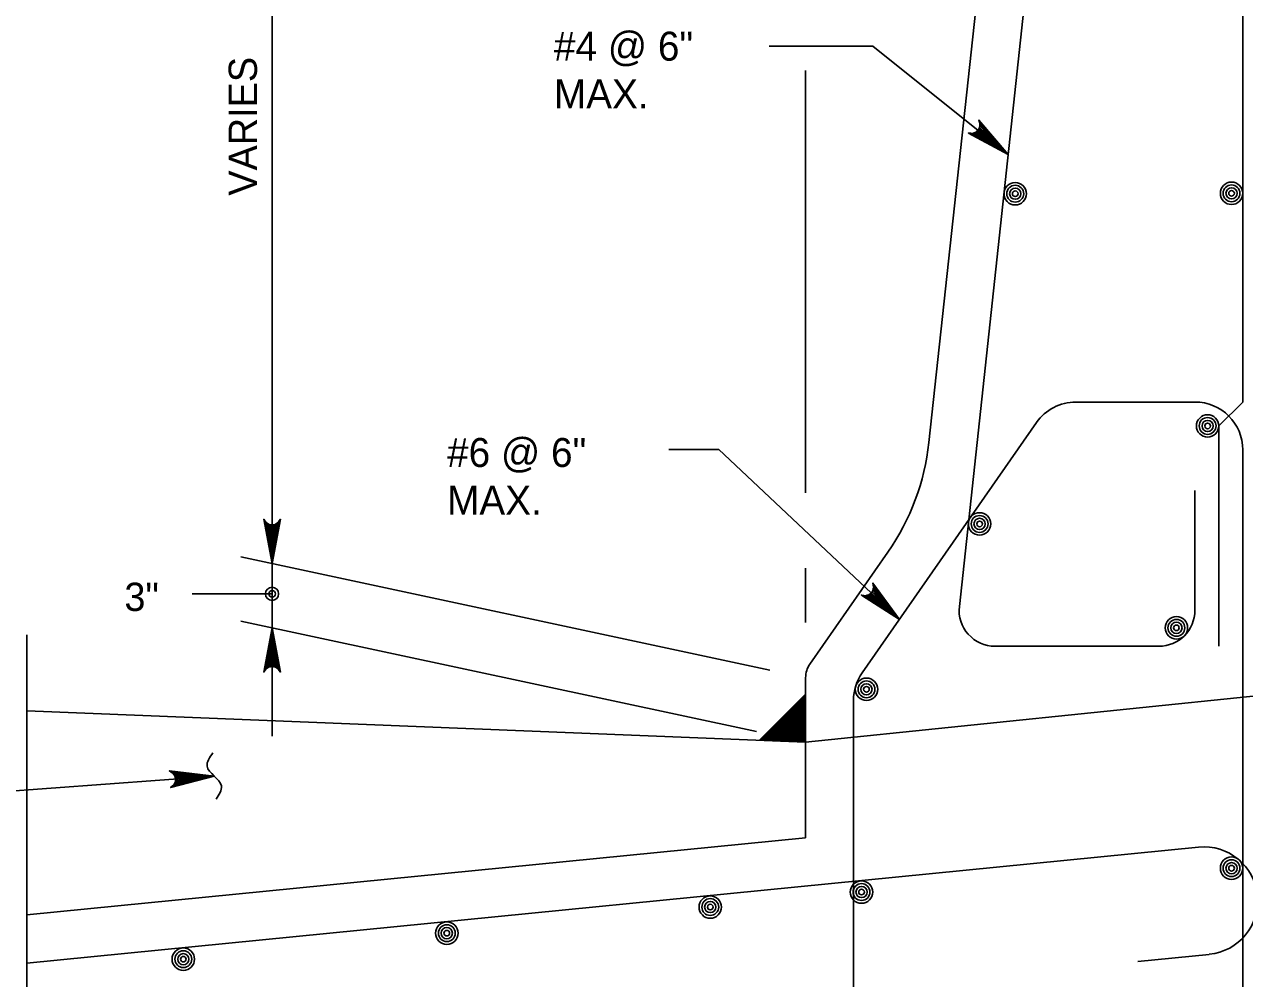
# Model space of a CAD drawing. Extents: x 638167 to 640248, y 296544 to 298920.
# Drawn here: x 639614.9 to 639744.3, y 297561.4 to 297662.6 of the extents above; entities that cross this region are included whole.
import ezdxf

# ---------------------------------------------------------------- set-up
doc = ezdxf.new("R2010")
doc.units = 0
for name, color, linetype in [('1', 7, 'Continuous'), ('50', 7, 'Continuous'), ('57', 7, 'Continuous')]:
    doc.layers.add(name, color=color, linetype=linetype)

# ---------------------------------------------------------------- blocks, each defined once
blk = doc.blocks.new('DIMDOT')
at = {"layer": '57'}
for radius in [2, 1]:
    blk.add_circle((0, 0), radius, dxfattribs=at)
blk = doc.blocks.new('BAR')
at = {"layer": '50'}
for radius in [2, 1.5, 1, 0.5]:
    blk.add_circle((0, 0), radius, dxfattribs=at)

msp = doc.modelspace()

# ---------------------------------------------------------------- linework, layer by layer
at = {"layer": '1'}
for p, q in [((639641.2, 297587.07), (639641.2, 297705.25)), ((639718.74, 297691.24), (639710.86, 297618.23)), ((639723.14, 297684.65), (639714.09, 297600.83)), ((639744.14, 297622.52), (639744.14, 297684.25)), ((639704.92, 297660.27), (639693.92, 297660.27)), ((639704.92, 297660.27), (639719.26, 297648.78)), ((639697.78, 297612.87), (639697.78, 297657.69)), ((639739.06, 297622.52), (639726.44, 297622.52)), ((639744.14, 297622.52), (639741.6, 297619.98)), ((639722.27, 297620.34), (639703.78, 297593.79)), ((639741.6, 297596.62), (639741.6, 297619.98)), ((639688.56, 297617.47), (639683.26, 297617.47)), ((639688.56, 297617.47), (639707.73, 297599.46)), ((639744.14, 297527.71), (639744.14, 297617.44)), ((639739.06, 297613.13), (639739.06, 297600.43)), ((639706.5, 297606.59), (639698.24, 297594.73)), ((639693.97, 297594.09), (639637.88, 297606.1)), ((639697.78, 297599.15), (639697.78, 297604.91)), ((639641.2, 297602.17), (639632.73, 297602.17)), ((639692.57, 297587.57), (639637.88, 297599.28)), ((639615.18, 297552.37), (639615.18, 297597.82)), ((639717.87, 297596.62), (639735.25, 297596.62)), ((639697.78, 297593.28), (639697.78, 297576.3)), ((639692.9, 297586.65), (639697.78, 297591.54)), ((639697.49, 297591.09), (639696.65, 297590.24)), ((639697.35, 297591.09), (639696.65, 297590.38)), ((639697.64, 297591.09), (639696.65, 297590.1)), ((639697.78, 297591.09), (639696.79, 297590.1)), ((639697.35, 297590.1), (639696.85, 297590.6)), ((639697.49, 297590.1), (639696.92, 297590.67)), ((639697.78, 297590.95), (639696.93, 297590.1)), ((639697.64, 297590.1), (639696.99, 297590.74)), ((639697.78, 297590.1), (639697.06, 297590.81)), ((639697.78, 297590.81), (639697.07, 297590.1)), ((639697.78, 297590.23), (639697.13, 297590.88)), ((639697.78, 297590.37), (639697.2, 297590.95)), ((639697.78, 297590.67), (639697.21, 297590.1)), ((639697.78, 297590.51), (639697.27, 297591.02)), ((639697.35, 297591.09), (639697.34, 297591.09)), ((639697.78, 297591.52), (639697.35, 297591.09)), ((639697.78, 297590.65), (639697.35, 297591.09)), ((639697.49, 297591.09), (639697.41, 297591.17)), ((639697.78, 297591.38), (639697.49, 297591.09)), ((639697.64, 297591.09), (639697.49, 297591.24)), ((639697.78, 297590.8), (639697.49, 297591.09)), ((639697.78, 297591.09), (639697.56, 297591.31)), ((639697.78, 297591.22), (639697.63, 297591.38)), ((639697.78, 297591.24), (639697.64, 297591.09)), ((639697.78, 297590.94), (639697.64, 297591.09)), ((639697.78, 297591.36), (639697.7, 297591.45)), ((639697.78, 297591.5), (639697.77, 297591.52)), ((639697.78, 297586.46), (639747.31, 297591.54)), ((639697.78, 297591.08), (639697.78, 297591.09)), ((639697.78, 297591.09), (639697.78, 297591.09)), ((639702.86, 297590.89), (639702.86, 297543.27)), ((639615.18, 297589.76), (639697.78, 297586.46)), ((639696.36, 297590.1), (639695.37, 297589.11)), ((639696.5, 297590.1), (639695.51, 297589.11)), ((639695.8, 297589.11), (639695.58, 297589.33)), ((639695.94, 297589.11), (639695.65, 297589.4)), ((639696.65, 297590.1), (639695.66, 297589.11)), ((639696.08, 297589.11), (639695.72, 297589.47)), ((639696.22, 297589.11), (639695.79, 297589.54)), ((639696.65, 297589.95), (639695.8, 297589.11)), ((639696.36, 297589.11), (639695.86, 297589.61)), ((639696.5, 297589.11), (639695.93, 297589.68)), ((639696.65, 297589.81), (639695.94, 297589.11)), ((639696.65, 297589.11), (639696, 297589.75)), ((639696.65, 297589.25), (639696.07, 297589.82)), ((639696.65, 297589.67), (639696.08, 297589.11)), ((639696.65, 297589.39), (639696.14, 297589.89)), ((639696.65, 297589.53), (639696.21, 297589.96)), ((639696.65, 297589.53), (639696.22, 297589.11)), ((639696.65, 297589.67), (639696.28, 297590.03)), ((639696.36, 297590.1), (639696.35, 297590.1)), ((639696.65, 297590.38), (639696.36, 297590.1)), ((639696.65, 297589.81), (639696.36, 297590.1)), ((639696.65, 297589.39), (639696.36, 297589.11)), ((639696.5, 297590.1), (639696.42, 297590.18)), ((639696.65, 297590.1), (639696.5, 297590.25)), ((639696.65, 297590.24), (639696.5, 297590.1)), ((639696.65, 297589.95), (639696.5, 297590.1)), ((639696.65, 297590.24), (639696.57, 297590.32)), ((639696.65, 297590.38), (639696.64, 297590.39)), ((639696.93, 297590.1), (639696.65, 297590.38)), ((639696.79, 297590.1), (639696.65, 297590.24)), ((639697.49, 297590.1), (639696.65, 297589.25)), ((639697.35, 297590.1), (639696.65, 297589.39)), ((639697.21, 297590.1), (639696.65, 297589.53)), ((639697.07, 297590.1), (639696.65, 297589.67)), ((639696.93, 297590.1), (639696.65, 297589.81)), ((639696.79, 297590.1), (639696.65, 297589.95)), ((639697.64, 297590.1), (639696.65, 297589.11)), ((639697.64, 297589.11), (639696.65, 297590.1)), ((639697.49, 297589.11), (639696.65, 297589.95)), ((639697.35, 297589.11), (639696.65, 297589.81)), ((639697.21, 297589.11), (639696.65, 297589.67)), ((639697.07, 297589.11), (639696.65, 297589.53)), ((639696.93, 297589.11), (639696.65, 297589.39)), ((639697.07, 297590.1), (639696.71, 297590.46)), ((639697.21, 297590.1), (639696.78, 297590.53)), ((639697.78, 297590.1), (639696.79, 297589.11)), ((639697.78, 297589.11), (639696.79, 297590.1)), ((639697.78, 297589.24), (639696.93, 297590.1)), ((639697.78, 297589.96), (639696.93, 297589.11)), ((639697.78, 297589.38), (639697.07, 297590.1)), ((639697.78, 297589.82), (639697.07, 297589.11)), ((639697.78, 297589.52), (639697.21, 297590.1)), ((639697.78, 297589.68), (639697.21, 297589.11)), ((639697.78, 297590.53), (639697.35, 297590.1)), ((639697.78, 297589.66), (639697.35, 297590.1)), ((639697.78, 297589.54), (639697.35, 297589.11)), ((639697.78, 297590.39), (639697.49, 297590.1)), ((639697.78, 297589.81), (639697.49, 297590.1)), ((639697.78, 297589.4), (639697.49, 297589.11)), ((639697.78, 297590.25), (639697.64, 297590.1)), ((639697.78, 297589.95), (639697.64, 297590.1)), ((639697.78, 297590.09), (639697.78, 297590.1)), ((639697.78, 297590.1), (639697.78, 297590.1)), ((639694.38, 297588.12), (639693.39, 297587.13)), ((639694.52, 297588.12), (639693.53, 297587.13)), ((639694.67, 297588.12), (639693.68, 297587.13)), ((639694.67, 297587.69), (639694.3, 297588.05)), ((639694.38, 297588.12), (639694.37, 297588.12)), ((639694.67, 297588.4), (639694.38, 297588.12)), ((639694.67, 297587.83), (639694.38, 297588.12)), ((639694.52, 297588.12), (639694.44, 297588.2)), ((639694.67, 297588.12), (639694.52, 297588.27)), ((639694.67, 297588.26), (639694.52, 297588.12)), ((639694.67, 297587.97), (639694.52, 297588.12)), ((639694.67, 297588.26), (639694.59, 297588.34)), ((639694.67, 297588.4), (639694.66, 297588.41)), ((639695.51, 297589.11), (639694.67, 297588.26)), ((639695.37, 297589.11), (639694.67, 297588.4)), ((639695.66, 297589.11), (639694.67, 297588.12)), ((639694.95, 297588.12), (639694.67, 297588.4)), ((639694.81, 297588.12), (639694.67, 297588.26)), ((639695.51, 297588.12), (639694.67, 297587.27)), ((639695.37, 297588.12), (639694.67, 297587.41)), ((639695.23, 297588.12), (639694.67, 297587.55)), ((639695.09, 297588.12), (639694.67, 297587.69)), ((639694.95, 297588.12), (639694.67, 297587.83)), ((639694.81, 297588.12), (639694.67, 297587.97)), ((639695.66, 297588.12), (639694.67, 297587.13)), ((639695.66, 297587.13), (639694.67, 297588.12)), ((639695.09, 297588.12), (639694.73, 297588.48)), ((639695.23, 297588.12), (639694.8, 297588.55)), ((639695.8, 297589.11), (639694.81, 297588.12)), ((639695.8, 297588.12), (639694.81, 297587.13)), ((639695.8, 297587.13), (639694.81, 297588.12)), ((639695.37, 297588.12), (639694.87, 297588.62)), ((639695.51, 297588.12), (639694.94, 297588.69)), ((639695.94, 297589.11), (639694.95, 297588.12)), ((639695.94, 297588.12), (639694.95, 297587.13)), ((639695.94, 297587.13), (639694.95, 297588.12)), ((639695.66, 297588.12), (639695.01, 297588.76)), ((639695.8, 297588.12), (639695.08, 297588.83)), ((639696.08, 297589.11), (639695.09, 297588.12)), ((639696.08, 297588.12), (639695.09, 297587.13)), ((639696.08, 297587.13), (639695.09, 297588.12)), ((639695.94, 297588.12), (639695.15, 297588.9)), ((639696.08, 297588.12), (639695.22, 297588.97)), ((639696.22, 297589.11), (639695.23, 297588.12)), ((639696.22, 297588.12), (639695.23, 297587.13)), ((639696.22, 297587.13), (639695.23, 297588.12)), ((639696.22, 297588.12), (639695.29, 297589.04)), ((639695.37, 297589.11), (639695.36, 297589.11)), ((639696.36, 297589.11), (639695.37, 297588.12)), ((639696.36, 297588.12), (639695.37, 297589.11)), ((639696.36, 297588.12), (639695.37, 297587.13)), ((639696.36, 297587.13), (639695.37, 297588.12)), ((639695.51, 297589.11), (639695.43, 297589.19)), ((639695.66, 297589.11), (639695.51, 297589.26)), ((639696.5, 297589.11), (639695.51, 297588.12)), ((639696.5, 297588.12), (639695.51, 297589.11)), ((639696.5, 297588.12), (639695.51, 297587.13)), ((639696.5, 297587.13), (639695.51, 297588.12)), ((639696.65, 297588.12), (639695.66, 297589.11)), ((639696.65, 297589.11), (639695.66, 297588.12)), ((639696.65, 297587.13), (639695.66, 297588.12)), ((639696.65, 297588.12), (639695.66, 297587.13)), ((639696.65, 297588.26), (639695.8, 297589.11)), ((639696.65, 297588.96), (639695.8, 297588.12)), ((639696.65, 297587.27), (639695.8, 297588.12)), ((639696.65, 297588.4), (639695.94, 297589.11)), ((639696.65, 297588.82), (639695.94, 297588.12)), ((639696.65, 297587.41), (639695.94, 297588.12)), ((639696.65, 297588.54), (639696.08, 297589.11)), ((639696.65, 297588.68), (639696.08, 297588.12)), ((639696.65, 297587.55), (639696.08, 297588.12)), ((639696.65, 297588.68), (639696.22, 297589.11)), ((639696.65, 297588.54), (639696.22, 297588.12)), ((639696.65, 297587.69), (639696.22, 297588.12)), ((639696.65, 297588.82), (639696.36, 297589.11)), ((639696.65, 297588.4), (639696.36, 297588.12)), ((639696.65, 297587.83), (639696.36, 297588.12)), ((639696.65, 297589.25), (639696.5, 297589.11)), ((639696.65, 297588.96), (639696.5, 297589.11)), ((639696.65, 297588.26), (639696.5, 297588.12)), ((639696.65, 297587.97), (639696.5, 297588.12)), ((639696.79, 297589.11), (639696.65, 297589.25)), ((639697.49, 297589.11), (639696.65, 297588.26)), ((639697.35, 297589.11), (639696.65, 297588.4)), ((639697.21, 297589.11), (639696.65, 297588.54)), ((639697.07, 297589.11), (639696.65, 297588.68)), ((639696.93, 297589.11), (639696.65, 297588.82)), ((639696.79, 297589.11), (639696.65, 297588.96)), ((639697.64, 297589.11), (639696.65, 297588.12)), ((639697.64, 297588.12), (639696.65, 297589.11)), ((639697.49, 297588.12), (639696.65, 297588.96)), ((639697.35, 297588.12), (639696.65, 297588.82)), ((639697.21, 297588.12), (639696.65, 297588.68)), ((639697.07, 297588.12), (639696.65, 297588.54)), ((639696.93, 297588.12), (639696.65, 297588.4)), ((639696.79, 297588.12), (639696.65, 297588.26)), ((639697.49, 297588.12), (639696.65, 297587.27)), ((639697.35, 297588.12), (639696.65, 297587.41)), ((639697.21, 297588.12), (639696.65, 297587.55)), ((639697.07, 297588.12), (639696.65, 297587.69)), ((639696.93, 297588.12), (639696.65, 297587.83)), ((639696.79, 297588.12), (639696.65, 297587.97)), ((639697.64, 297588.12), (639696.65, 297587.13)), ((639697.64, 297587.13), (639696.65, 297588.12)), ((639697.78, 297589.11), (639696.79, 297588.12)), ((639697.78, 297588.12), (639696.79, 297589.11)), ((639697.78, 297588.12), (639696.79, 297587.13)), ((639697.78, 297587.13), (639696.79, 297588.12)), ((639697.78, 297588.25), (639696.93, 297589.11)), ((639697.78, 297588.97), (639696.93, 297588.12)), ((639697.78, 297587.26), (639696.93, 297588.12)), ((639697.78, 297588.39), (639697.07, 297589.11)), ((639697.78, 297588.83), (639697.07, 297588.12)), ((639697.78, 297587.4), (639697.07, 297588.12)), ((639697.78, 297588.53), (639697.21, 297589.11)), ((639697.78, 297588.69), (639697.21, 297588.12)), ((639697.78, 297587.54), (639697.21, 297588.12)), ((639697.78, 297588.67), (639697.35, 297589.11)), ((639697.78, 297588.55), (639697.35, 297588.12)), ((639697.78, 297587.68), (639697.35, 297588.12)), ((639697.78, 297588.82), (639697.49, 297589.11)), ((639697.78, 297588.41), (639697.49, 297588.12)), ((639697.78, 297587.83), (639697.49, 297588.12)), ((639697.78, 297589.26), (639697.64, 297589.11)), ((639697.78, 297588.96), (639697.64, 297589.11)), ((639697.78, 297588.27), (639697.64, 297588.12)), ((639697.78, 297587.97), (639697.64, 297588.12)), ((639697.78, 297589.1), (639697.78, 297589.11)), ((639697.78, 297589.11), (639697.78, 297589.11)), ((639697.78, 297588.11), (639697.78, 297588.12)), ((639697.78, 297588.12), (639697.78, 297588.12)), ((639693.39, 297587.13), (639692.92, 297586.65)), ((639693.02, 297586.65), (639692.96, 297586.71)), ((639693.17, 297586.64), (639693.03, 297586.78)), ((639693.53, 297587.13), (639693.05, 297586.64)), ((639693.32, 297586.63), (639693.1, 297586.85)), ((639693.47, 297586.63), (639693.17, 297586.92)), ((639693.68, 297587.13), (639693.19, 297586.64)), ((639693.61, 297586.62), (639693.24, 297586.99)), ((639693.76, 297586.62), (639693.31, 297587.06)), ((639693.82, 297587.13), (639693.33, 297586.63)), ((639693.39, 297587.13), (639693.38, 297587.13)), ((639693.91, 297586.61), (639693.39, 297587.13)), ((639693.53, 297587.13), (639693.45, 297587.21)), ((639693.96, 297587.13), (639693.46, 297586.63)), ((639693.68, 297587.13), (639693.53, 297587.28)), ((639694.06, 297586.6), (639693.53, 297587.13)), ((639693.82, 297587.13), (639693.6, 297587.35)), ((639694.1, 297587.13), (639693.6, 297586.62)), ((639693.96, 297587.13), (639693.67, 297587.42)), ((639694.2, 297586.6), (639693.68, 297587.13)), ((639694.24, 297587.13), (639693.73, 297586.62)), ((639694.1, 297587.13), (639693.74, 297587.49)), ((639694.24, 297587.13), (639693.81, 297587.56)), ((639694.67, 297587.97), (639693.82, 297587.13)), ((639694.35, 297586.59), (639693.82, 297587.13)), ((639694.38, 297587.13), (639693.87, 297586.61)), ((639694.38, 297587.13), (639693.88, 297587.63)), ((639694.52, 297587.13), (639693.95, 297587.7)), ((639694.67, 297587.83), (639693.96, 297587.13)), ((639694.5, 297586.59), (639693.96, 297587.13)), ((639694.52, 297587.13), (639694, 297586.61)), ((639694.67, 297587.13), (639694.02, 297587.77)), ((639694.67, 297587.27), (639694.09, 297587.84)), ((639694.67, 297587.69), (639694.1, 297587.13)), ((639694.64, 297586.58), (639694.1, 297587.13)), ((639694.67, 297587.13), (639694.14, 297586.6)), ((639694.67, 297587.41), (639694.16, 297587.91)), ((639694.67, 297587.55), (639694.23, 297587.98)), ((639694.67, 297587.55), (639694.24, 297587.13)), ((639694.67, 297586.7), (639694.24, 297587.13)), ((639694.67, 297586.98), (639694.28, 297586.6)), ((639694.67, 297587.41), (639694.38, 297587.13)), ((639694.67, 297586.84), (639694.38, 297587.13)), ((639694.67, 297586.84), (639694.41, 297586.59)), ((639694.67, 297587.27), (639694.52, 297587.13)), ((639694.67, 297586.98), (639694.52, 297587.13)), ((639694.67, 297586.7), (639694.55, 297586.59)), ((639695.51, 297587.13), (639694.67, 297587.97)), ((639695.37, 297587.13), (639694.67, 297587.83)), ((639695.23, 297587.13), (639694.67, 297587.69)), ((639695.09, 297587.13), (639694.67, 297587.55)), ((639694.95, 297587.13), (639694.67, 297587.41)), ((639694.81, 297587.13), (639694.67, 297587.27)), ((639695.09, 297587.13), (639694.67, 297586.7)), ((639694.95, 297587.13), (639694.67, 297586.84)), ((639694.81, 297587.13), (639694.67, 297586.98)), ((639695.23, 297586.56), (639694.67, 297587.13)), ((639695.09, 297586.56), (639694.67, 297586.98)), ((639694.94, 297586.57), (639694.67, 297586.84)), ((639694.79, 297586.58), (639694.67, 297586.7)), ((639695.23, 297587.13), (639694.68, 297586.58)), ((639695.38, 297586.55), (639694.81, 297587.13)), ((639695.37, 297587.13), (639694.82, 297586.57)), ((639695.53, 297586.55), (639694.95, 297587.13)), ((639695.51, 297587.13), (639694.96, 297586.57)), ((639695.68, 297586.54), (639695.09, 297587.13)), ((639695.66, 297587.13), (639695.09, 297586.56)), ((639695.8, 297587.13), (639695.23, 297586.56)), ((639695.82, 297586.53), (639695.23, 297587.13)), ((639695.94, 297587.13), (639695.36, 297586.55)), ((639695.97, 297586.53), (639695.37, 297587.13)), ((639696.08, 297587.13), (639695.5, 297586.55)), ((639696.12, 297586.52), (639695.51, 297587.13)), ((639696.22, 297587.13), (639695.64, 297586.54)), ((639696.27, 297586.52), (639695.66, 297587.13)), ((639696.36, 297587.13), (639695.77, 297586.54)), ((639696.65, 297587.97), (639695.8, 297587.13)), ((639696.41, 297586.51), (639695.8, 297587.13)), ((639696.5, 297587.13), (639695.91, 297586.53)), ((639696.65, 297587.83), (639695.94, 297587.13)), ((639696.56, 297586.5), (639695.94, 297587.13)), ((639696.65, 297587.13), (639696.04, 297586.53)), ((639696.65, 297587.69), (639696.08, 297587.13)), ((639696.65, 297586.56), (639696.08, 297587.13)), ((639696.65, 297586.98), (639696.18, 297586.52)), ((639696.65, 297587.55), (639696.22, 297587.13)), ((639696.65, 297586.7), (639696.22, 297587.13)), ((639696.65, 297586.84), (639696.32, 297586.51)), ((639696.65, 297587.41), (639696.36, 297587.13)), ((639696.65, 297586.84), (639696.36, 297587.13)), ((639696.65, 297586.7), (639696.45, 297586.51)), ((639696.65, 297587.27), (639696.5, 297587.13)), ((639696.65, 297586.98), (639696.5, 297587.13)), ((639697.49, 297587.13), (639696.65, 297587.97)), ((639697.35, 297587.13), (639696.65, 297587.83)), ((639697.21, 297587.13), (639696.65, 297587.69)), ((639697.07, 297587.13), (639696.65, 297587.55)), ((639696.93, 297587.13), (639696.65, 297587.41)), ((639696.79, 297587.13), (639696.65, 297587.27)), ((639697.21, 297587.13), (639696.65, 297586.56)), ((639697.07, 297587.13), (639696.65, 297586.7)), ((639696.93, 297587.13), (639696.65, 297586.84)), ((639696.79, 297587.13), (639696.65, 297586.98)), ((639697.3, 297586.48), (639696.65, 297587.13)), ((639697.15, 297586.48), (639696.65, 297586.98)), ((639697, 297586.49), (639696.65, 297586.84)), ((639696.85, 297586.49), (639696.65, 297586.7)), ((639697.35, 297587.13), (639696.72, 297586.5)), ((639697.44, 297586.47), (639696.79, 297587.13)), ((639697.49, 297587.13), (639696.86, 297586.49)), ((639697.78, 297587.98), (639696.93, 297587.13)), ((639697.59, 297586.46), (639696.93, 297587.13)), ((639697.64, 297587.13), (639697, 297586.49)), ((639697.78, 297587.84), (639697.07, 297587.13)), ((639697.74, 297586.46), (639697.07, 297587.13)), ((639697.78, 297587.13), (639697.13, 297586.48)), ((639697.78, 297587.7), (639697.21, 297587.13)), ((639697.78, 297586.55), (639697.21, 297587.13)), ((639697.78, 297586.99), (639697.27, 297586.48)), ((639697.78, 297587.56), (639697.35, 297587.13)), ((639697.78, 297586.69), (639697.35, 297587.13)), ((639697.78, 297586.85), (639697.4, 297586.47)), ((639697.78, 297587.42), (639697.49, 297587.13)), ((639697.78, 297586.84), (639697.49, 297587.13)), ((639697.78, 297586.71), (639697.54, 297586.47)), ((639697.78, 297587.28), (639697.64, 297587.13)), ((639697.78, 297586.98), (639697.64, 297587.13)), ((639697.78, 297587.12), (639697.78, 297587.13)), ((639697.78, 297587.13), (639697.78, 297587.13)), ((639696.65, 297586.56), (639696.59, 297586.5)), ((639696.71, 297586.5), (639696.65, 297586.56)), ((639697.78, 297586.57), (639697.68, 297586.46)), ((639606.73, 297580.76), (639635.06, 297582.85)), ((639697.78, 297576.3), (639615.18, 297568.12)), ((639739.46, 297575.31), (639615.18, 297563.02)), ((639733, 297563.19), (639740.58, 297563.94))]:
    msp.add_line(p, q, dxfattribs=at)
for points in [[(639719.26, 297648.78), (639716.15, 297652.41), (639716.21, 297652.2), (639716.27, 297651.99), (639716.25, 297651.8), (639716.22, 297651.62), (639716.15, 297651.48), (639716.07, 297651.34), (639715.95, 297651.24), (639715.83, 297651.13), (639715.66, 297651.07), (639715.49, 297651), (639715.27, 297651.02), (639715.05, 297651.03), (639719.26, 297648.78), (639715.27, 297651.02), (639715.49, 297651), (639719.26, 297648.78), (639715.66, 297651.07), (639715.83, 297651.13), (639719.26, 297648.78), (639715.95, 297651.24), (639716.07, 297651.34), (639719.26, 297648.78), (639716.15, 297651.48), (639716.22, 297651.62), (639719.26, 297648.78), (639716.25, 297651.8), (639716.27, 297651.99), (639719.26, 297648.78), (639716.21, 297652.2)], [(639641.2, 297605.39), (639640.32, 297610.09), (639640.45, 297609.91), (639640.57, 297609.73), (639640.73, 297609.63), (639640.89, 297609.54), (639641.04, 297609.51), (639641.2, 297609.49), (639641.36, 297609.51), (639641.52, 297609.54), (639641.67, 297609.63), (639641.83, 297609.73), (639641.96, 297609.91), (639642.08, 297610.09), (639641.2, 297605.39), (639641.96, 297609.91), (639641.83, 297609.73), (639641.2, 297605.39), (639641.67, 297609.63), (639641.52, 297609.54), (639641.2, 297605.39), (639641.36, 297609.51), (639641.2, 297609.49), (639641.2, 297605.39), (639641.04, 297609.51), (639640.89, 297609.54), (639641.2, 297605.39), (639640.73, 297609.63), (639640.57, 297609.73), (639641.2, 297605.39), (639640.45, 297609.91)], [(639707.73, 297599.46), (639703.7, 297602.04), (639703.92, 297602), (639704.13, 297601.97), (639704.31, 297602.02), (639704.49, 297602.07), (639704.61, 297602.17), (639704.74, 297602.26), (639704.83, 297602.4), (639704.92, 297602.53), (639704.96, 297602.71), (639705, 297602.89), (639704.95, 297603.1), (639704.91, 297603.32), (639707.73, 297599.46), (639704.95, 297603.1), (639705, 297602.89), (639707.73, 297599.46), (639704.96, 297602.71), (639704.92, 297602.53), (639707.73, 297599.46), (639704.83, 297602.4), (639704.74, 297602.26), (639707.73, 297599.46), (639704.61, 297602.17), (639704.49, 297602.07), (639707.73, 297599.46), (639704.31, 297602.02), (639704.13, 297601.97), (639707.73, 297599.46), (639703.92, 297602)], [(639641.2, 297598.57), (639642.08, 297593.87), (639641.96, 297594.05), (639641.83, 297594.23), (639641.67, 297594.33), (639641.52, 297594.42), (639641.36, 297594.45), (639641.2, 297594.47), (639641.04, 297594.45), (639640.89, 297594.42), (639640.73, 297594.33), (639640.57, 297594.23), (639640.45, 297594.05), (639640.32, 297593.87), (639641.2, 297598.57), (639640.45, 297594.05), (639640.57, 297594.23), (639641.2, 297598.57), (639640.73, 297594.33), (639640.89, 297594.42), (639641.2, 297598.57), (639641.04, 297594.45), (639641.2, 297594.47), (639641.2, 297598.57), (639641.36, 297594.45), (639641.52, 297594.42), (639641.2, 297598.57), (639641.67, 297594.33), (639641.83, 297594.23), (639641.2, 297598.57), (639641.96, 297594.05)], [(639635.06, 297582.85), (639630.44, 297581.63), (639630.61, 297581.77), (639630.78, 297581.91), (639630.87, 297582.07), (639630.95, 297582.23), (639630.96, 297582.39), (639630.98, 297582.55), (639630.94, 297582.71), (639630.9, 297582.86), (639630.8, 297583.01), (639630.69, 297583.16), (639630.5, 297583.27), (639630.31, 297583.39), (639635.06, 297582.85), (639630.5, 297583.27), (639630.69, 297583.16), (639635.06, 297582.85), (639630.8, 297583.01), (639630.9, 297582.86), (639635.06, 297582.85), (639630.94, 297582.71), (639630.98, 297582.55), (639635.06, 297582.85), (639630.96, 297582.39), (639630.95, 297582.23), (639635.06, 297582.85), (639630.87, 297582.07), (639630.78, 297581.91), (639635.06, 297582.85), (639630.61, 297581.77)]]:
    msp.add_lwpolyline(points, dxfattribs=at)
for centre, radius, start, end in [((639726.44, 297617.44), 5.08, 90, 145.1455), ((639739.06, 297617.44), 5.08, 0, 90), ((639685.92, 297620.93), 25.08, 325.1455, 353.8367), ((639717.87, 297600.43), 3.81, 173.8367, 270), ((639735.25, 297600.43), 3.81, 270, 0), ((639700.32, 297593.28), 2.54, 145.1455, 180), ((639707.94, 297590.89), 5.08, 145.1455, 180), ((639740.02, 297569.63), 5.71, 275.6517, 95.6517)]:
    msp.add_arc(centre, radius, start, end, dxfattribs=at)
msp.add_spline([(639634.93, 297585.31), (639634.31, 297583.9), (639635.83, 297581.8), (639635.27, 297580.41)], degree=3, dxfattribs=at)

# ---------------------------------------------------------------- block references
at = {"layer": '1', "xscale": 0.5953136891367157, "yscale": -0.5953136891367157, "rotation": -89.99999999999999}
for p in [(639720.01, 297644.61), (639742.95, 297644.65), (639740.41, 297619.98), (639716.23, 297609.59), (639737.1, 297598.57), (639704.23, 297592.05), (639742.95, 297573.08), (639703.71, 297570.55), (639687.67, 297568.96), (639659.73, 297566.19), (639631.79, 297563.43)]:
    msp.add_blockref('BAR', p, dxfattribs=at)
at = {"layer": '1', "xscale": 0.349999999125, "yscale": 0.349999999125}
msp.add_blockref('DIMDOT', (639641.2, 297602.17), dxfattribs=at)

# ---------------------------------------------------------------- texts
at = {"layer": '1'}
for s, height, rotation, p in [('#4 @ 6"', 3.072, 360, (639671.09, 297658.72)), ('VARIES', 3, 90, (639639.6, 297644.4)), ('MAX.', 3.072, 360, (639671.09, 297653.65)), ('#6 @ 6"', 3.072, 360, (639659.76, 297615.63)), ('MAX.', 3.072, 360, (639659.76, 297610.56))]:
    msp.add_text(s, height=height, rotation=rotation, dxfattribs=at).set_placement(p)
msp.add_text('3"', height=3, dxfattribs=at).set_placement((639625.54, 297600.36))

doc.saveas('drawing.dxf')
